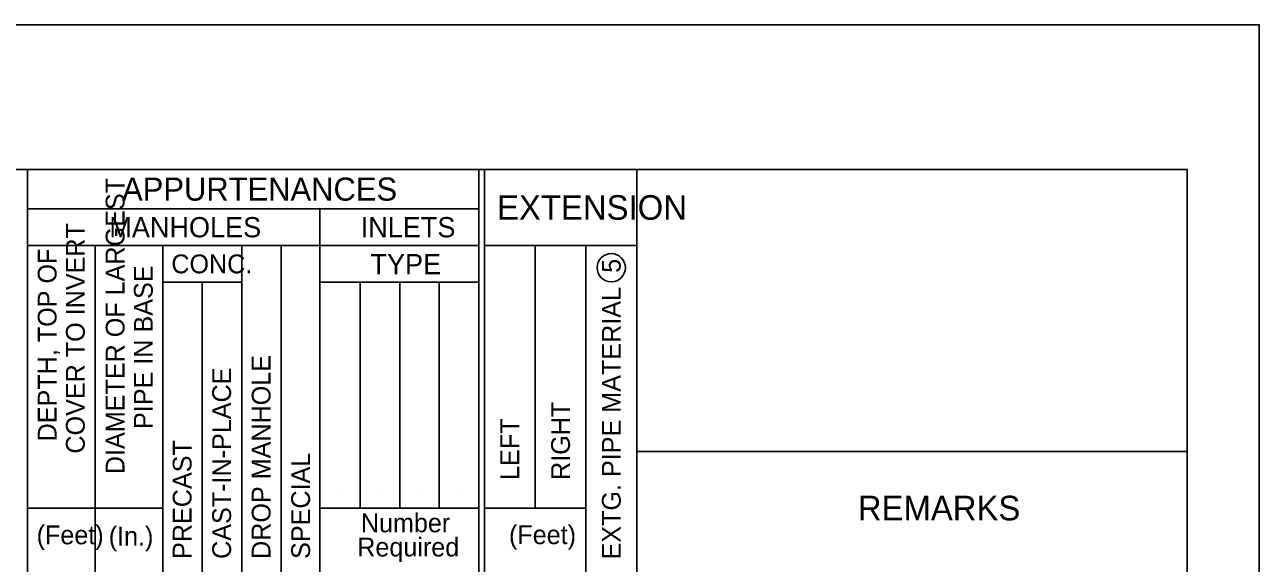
# Model space of a CAD drawing. Extents: x 0 to 1.42, y 0 to 0.92.
# Drawn here: x 1.0608 to 1.4167, y 0.7615 to 0.9167 of the extents above; entities that cross this region are included whole.
import ezdxf

# ---------------------------------------------------------------- set-up
doc = ezdxf.new("R2010")
doc.units = 0
for name, color, linetype in [('#plot_shape', 7, 'Continuous'), ('P_ODOT_PLAN_Border', 7, 'Continuous'), ('P_ODOT_PLAN_General', 7, 'Continuous'), ('P_RDWY_PLAN_NotesTx', 7, 'Continuous')]:
    doc.layers.add(name, color=color, linetype=linetype)

msp = doc.modelspace()

# ---------------------------------------------------------------- linework, layer by layer
at = {"layer": '#plot_shape'}
msp.add_lwpolyline([(0, 0), (1.41667, 0), (1.41667, 0.91667), (0, 0.91667)], close=True, dxfattribs=at)
at = {"layer": 'P_ODOT_PLAN_Border'}
msp.add_lwpolyline([(0.0625, 0.04167), (1.39583, 0.04167), (1.39583, 0.875), (0.0625, 0.875)], close=True, dxfattribs=at)
at = {"layer": 'P_ODOT_PLAN_General'}
for p, q in [((1.06165, 0.26037), (1.06165, 0.875)), ((1.1917, 0.26037), (1.1917, 0.875)), ((1.19333, 0.26037), (1.19333, 0.875)), ((1.23723, 0.26037), (1.23723, 0.875)), ((1.1917, 0.86362), (1.06165, 0.86362)), ((1.14594, 0.26037), (1.14594, 0.86362)), ((1.1917, 0.85305), (1.06165, 0.85305)), ((1.08115, 0.26037), (1.08115, 0.85305)), ((1.10065, 0.26037), (1.10065, 0.85305)), ((1.12341, 0.26037), (1.12341, 0.85305)), ((1.13479, 0.26037), (1.13479, 0.85305)), ((1.23723, 0.85305), (1.19333, 0.85305)), ((1.20796, 0.77744), (1.20796, 0.85305)), ((1.2226, 0.26037), (1.2226, 0.85305)), ((1.12341, 0.84248), (1.10065, 0.84248)), ((1.11203, 0.26037), (1.11203, 0.84248)), ((1.1917, 0.84248), (1.14594, 0.84248)), ((1.15756, 0.77744), (1.15756, 0.84248)), ((1.16894, 0.77744), (1.16894, 0.84248)), ((1.18032, 0.77744), (1.18032, 0.84248)), ((1.23723, 0.7937), (1.39583, 0.7937)), ((1.10065, 0.77744), (1.06165, 0.77744)), ((1.1917, 0.77744), (1.14594, 0.77744)), ((1.2226, 0.77744), (1.19333, 0.77744))]:
    msp.add_line(p, q, dxfattribs=at)
at = {"layer": 'P_RDWY_PLAN_NotesTx'}
for p, q in [((1.15187, 0.78161), (1.15187, 0.78161)), ((1.16325, 0.78161), (1.16325, 0.78161)), ((1.17463, 0.78161), (1.17463, 0.78161)), ((1.18601, 0.78161), (1.18601, 0.78161)), ((1.10622, 0.76278), (1.10622, 0.76278)), ((1.1176, 0.76278), (1.1176, 0.76278)), ((1.12899, 0.76278), (1.12899, 0.76278)), ((1.14037, 0.76278), (1.14037, 0.76278))]:
    msp.add_line(p, q, dxfattribs=at)
msp.add_circle((1.2299, 0.84667), 0.00407, dxfattribs=at)

# ---------------------------------------------------------------- texts
for s, height, p in [('DIAMETER OF LARGEST', 0.0054167, (1.08961, 0.7872)), ('COVER TO INVERT', 0.0054167, (1.07815, 0.79312)), ('DEPTH, TOP OF', 0.0054167, (1.07002, 0.79664)), ('PIPE IN BASE', 0.0054167, (1.09774, 0.80022)), ('5', 0.00542, (1.23261, 0.84521)), ('EXTG. PIPE MATERIAL', 0.0054167, (1.23262, 0.76263)), ('DROP MANHOLE', 0.0054167, (1.13169, 0.76278)), ('CAST-IN-PLACE', 0.0054167, (1.12031, 0.76278)), ('RIGHT', 0.005417, (1.21799, 0.78553)), ('LEFT', 0.005417, (1.20336, 0.78553)), ('PRECAST', 0.005417, (1.10893, 0.76278)), ('SPECIAL', 0.005417, (1.14308, 0.76278))]:
    msp.add_text(s, height=height, rotation=90, dxfattribs=at).set_placement(p)
for s, height, p in [('APPURTENANCES', 0.0066667, (1.08891, 0.86598)), ('EXTENSION', 0.007083, (1.19697, 0.86048)), ('MANHOLES', 0.005833, (1.08522, 0.85542)), ('INLETS', 0.005833, (1.15767, 0.85542)), ('CONC.', 0.005417, (1.1031, 0.84506)), ('TYPE', 0.005833, (1.16049, 0.84478)), ('REMARKS', 0.007083, (1.30096, 0.7739)), ('Number', 0.005417, (1.15772, 0.77046)), ('(Feet)', 0.005417, (1.06428, 0.767)), ('(In.)', 0.005417, (1.08505, 0.76663)), ('(Feet)', 0.005417, (1.20042, 0.76705)), ('Required', 0.005417, (1.15668, 0.7635))]:
    msp.add_text(s, height=height, dxfattribs=at).set_placement(p)

doc.saveas('drawing.dxf')
